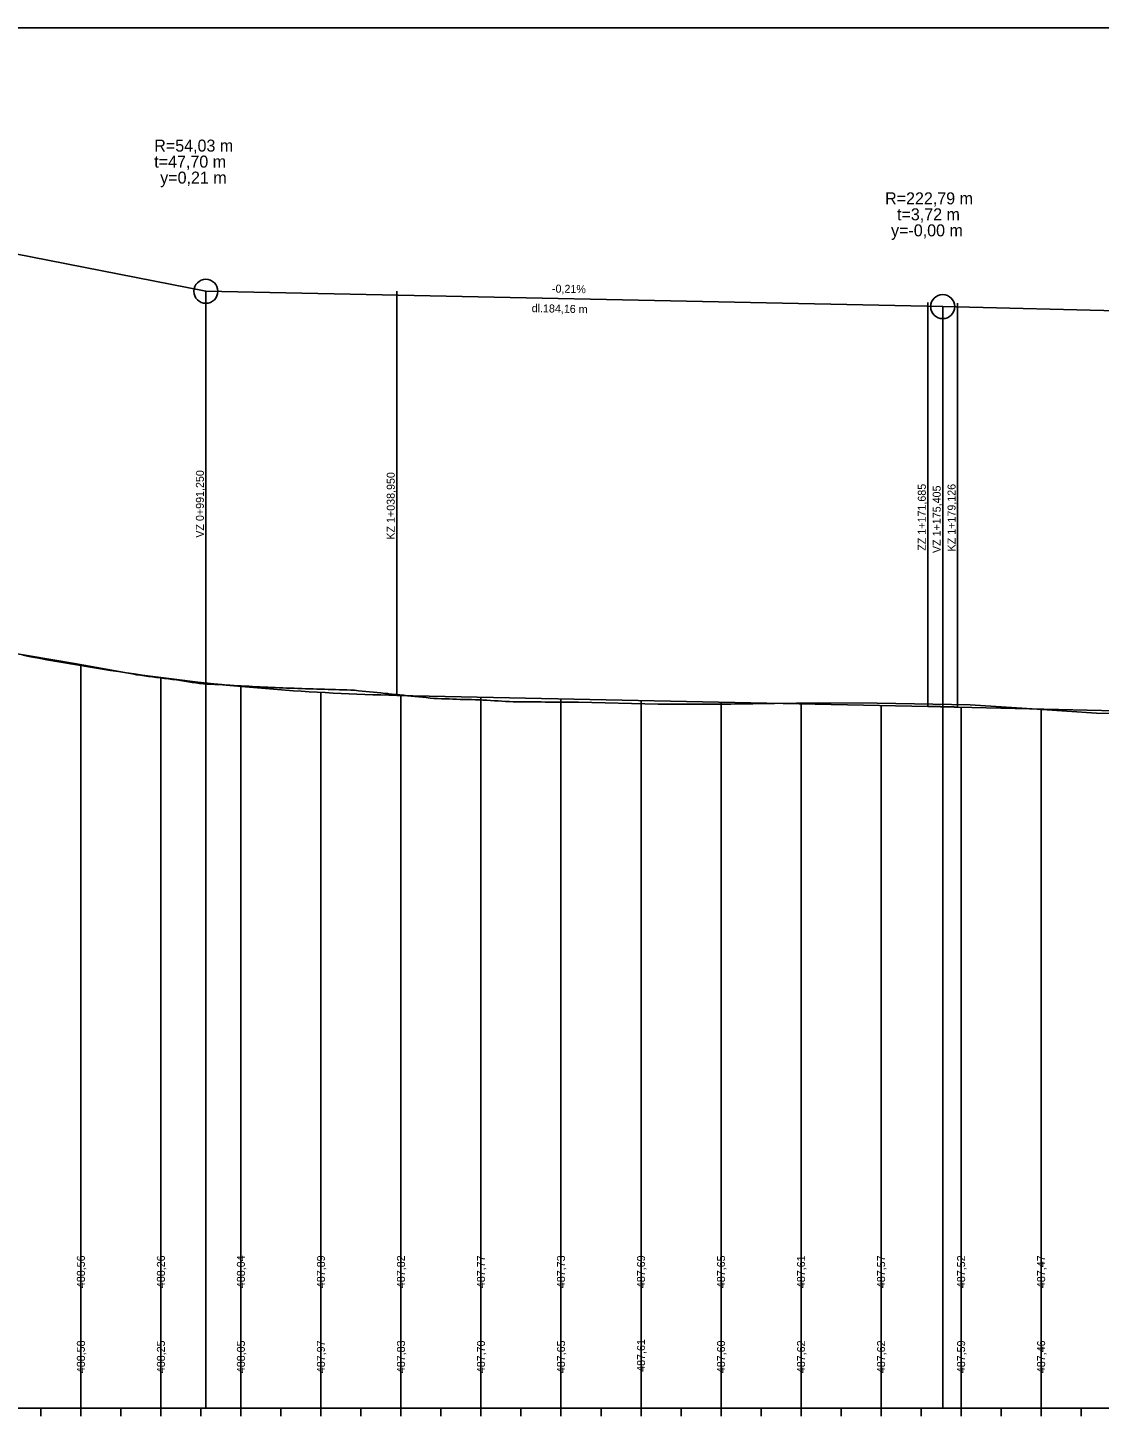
# Model space of a CAD drawing. Extents: x -632716 to -629545, y -1094726 to -1088285.
# Drawn here: x -631536.7 to -631269, y -1091019.4 to -1090670.2 of the extents above; entities that cross this region are included whole.
import ezdxf

# ---------------------------------------------------------------- set-up
doc = ezdxf.new("R2010")
doc.units = 0
for name, color, linetype in [('20', 7, 'Continuous'), ('Default', 7, 'Continuous'), ('formát', 7, 'Continuous'), ('NIVELETA_VYSKY', 7, 'Continuous'), ('REZ_TENKA', 7, 'Continuous'), ('REZ_TLUSTA', 7, 'Continuous'), ('SKLONY_NIVELETA', 7, 'Continuous'), ('SKLONY_POPIS', 7, 'Continuous'), ('TECNY_NIVELETA', 7, 'Continuous'), ('TEREN_VYSKY', 7, 'Continuous'), ('VOZOVKA', 7, 'Continuous')]:
    doc.layers.add(name, color=color, linetype=linetype)

msp = doc.modelspace()

# ---------------------------------------------------------------- linework, layer by layer
at = {"layer": '20'}
for points in [[(-631523.46, -1090829.61), (-631523.46, -1090965.2), (-631523.46, -1091015.2), (-631523.46, -1090955.2)], [(-631503.46, -1090832.58), (-631503.46, -1090965.2), (-631503.46, -1091015.2), (-631503.46, -1090955.2)], [(-631483.46, -1090834.8), (-631483.46, -1090965.2), (-631483.46, -1091015.2), (-631483.46, -1090955.2)], [(-631463.46, -1090836.29), (-631463.46, -1090965.2), (-631463.46, -1091015.2), (-631463.46, -1090955.2)], [(-631443.46, -1090837.04), (-631443.46, -1090965.2), (-631443.46, -1091015.2), (-631443.46, -1090955.2)], [(-631423.46, -1090837.46), (-631423.46, -1090965.2), (-631423.46, -1091015.2), (-631423.46, -1090955.2)], [(-631403.46, -1090837.88), (-631403.46, -1090965.2), (-631403.46, -1091015.2), (-631403.46, -1090955.2)], [(-631383.46, -1090838.29), (-631383.46, -1090965.2), (-631383.46, -1091015.2), (-631383.46, -1090955.2)], [(-631363.46, -1090838.71), (-631363.46, -1090965.2), (-631363.46, -1091015.2), (-631363.46, -1090955.2)], [(-631343.46, -1090839.13), (-631343.46, -1090965.2), (-631343.46, -1091015.2), (-631343.46, -1090955.2)], [(-631323.46, -1090839.54), (-631323.46, -1090965.2), (-631323.46, -1091015.2), (-631323.46, -1090955.2)], [(-631303.46, -1090839.98), (-631303.46, -1090965.2), (-631303.46, -1091015.2), (-631303.46, -1090955.2)], [(-631283.46, -1090840.46), (-631283.46, -1090965.2), (-631283.46, -1091015.2), (-631283.46, -1090955.2)]]:
    msp.add_lwpolyline(points, dxfattribs=at)
at = {"layer": 'Default'}
for p, q in [((-631444.51, -1090837.02), (-631311.78, -1090839.79)), ((-631444.51, -1090837.02), (-631311.78, -1090839.79)), ((-631304.34, -1090839.95), (-631176.44, -1090843.05)), ((-631304.34, -1090839.95), (-631176.44, -1090843.05))]:
    msp.add_line(p, q, dxfattribs=at)
for points in [[(-631537.93, -1090827), (-631535.94, -1090827.38), (-631533.95, -1090827.75), (-631531.96, -1090828.12), (-631529.98, -1090828.48), (-631527.99, -1090828.83), (-631526, -1090829.18), (-631524.01, -1090829.51), (-631522.03, -1090829.84), (-631520.04, -1090830.17), (-631518.05, -1090830.48), (-631516.06, -1090830.79), (-631514.08, -1090831.09), (-631512.09, -1090831.39), (-631510.1, -1090831.67), (-631508.11, -1090831.95), (-631506.13, -1090832.22), (-631504.14, -1090832.49), (-631502.15, -1090832.74), (-631500.16, -1090832.99), (-631498.18, -1090833.24), (-631496.19, -1090833.47), (-631494.2, -1090833.7), (-631490.23, -1090834.13), (-631488.24, -1090834.34), (-631486.25, -1090834.54), (-631484.26, -1090834.73), (-631482.28, -1090834.91), (-631480.29, -1090835.09), (-631478.3, -1090835.26), (-631476.31, -1090835.42), (-631474.33, -1090835.58), (-631472.34, -1090835.72), (-631470.35, -1090835.86), (-631468.36, -1090836), (-631466.38, -1090836.12), (-631464.39, -1090836.24), (-631462.4, -1090836.35), (-631460.41, -1090836.45), (-631458.43, -1090836.55), (-631456.44, -1090836.64), (-631454.45, -1090836.72), (-631452.46, -1090836.8), (-631450.48, -1090836.86), (-631448.49, -1090836.92), (-631446.5, -1090836.97), (-631444.51, -1090837.02)], [(-631537.93, -1090827), (-631535.94, -1090827.38), (-631533.95, -1090827.75), (-631531.96, -1090828.12), (-631529.98, -1090828.48), (-631527.99, -1090828.83), (-631526, -1090829.18), (-631524.01, -1090829.51), (-631522.03, -1090829.84), (-631520.04, -1090830.17), (-631518.05, -1090830.48), (-631516.06, -1090830.79), (-631514.08, -1090831.09), (-631512.09, -1090831.39), (-631510.1, -1090831.67), (-631508.11, -1090831.95), (-631506.13, -1090832.22), (-631504.14, -1090832.49), (-631502.15, -1090832.74), (-631500.16, -1090832.99), (-631498.18, -1090833.24), (-631496.19, -1090833.47), (-631494.2, -1090833.7), (-631490.23, -1090834.13), (-631488.24, -1090834.34), (-631486.25, -1090834.54), (-631484.26, -1090834.73), (-631482.28, -1090834.91), (-631480.29, -1090835.09), (-631478.3, -1090835.26), (-631476.31, -1090835.42), (-631474.33, -1090835.58), (-631472.34, -1090835.72), (-631470.35, -1090835.86), (-631468.36, -1090836), (-631466.38, -1090836.12), (-631464.39, -1090836.24), (-631462.4, -1090836.35), (-631460.41, -1090836.45), (-631458.43, -1090836.55), (-631456.44, -1090836.64), (-631454.45, -1090836.72), (-631452.46, -1090836.8), (-631450.48, -1090836.86), (-631448.49, -1090836.92), (-631446.5, -1090836.97), (-631444.51, -1090837.02)], [(-631311.78, -1090839.79), (-631311.62, -1090839.79), (-631311.47, -1090839.79), (-631311.31, -1090839.8), (-631311.16, -1090839.8), (-631311, -1090839.8), (-631310.85, -1090839.81), (-631310.69, -1090839.81), (-631310.54, -1090839.81), (-631310.38, -1090839.82), (-631310.23, -1090839.82), (-631310.07, -1090839.82), (-631309.92, -1090839.83), (-631309.76, -1090839.83), (-631309.61, -1090839.83), (-631309.45, -1090839.84), (-631309.3, -1090839.84), (-631309.14, -1090839.84), (-631308.99, -1090839.85), (-631308.83, -1090839.85), (-631308.68, -1090839.85), (-631308.52, -1090839.86), (-631308.37, -1090839.86), (-631308.21, -1090839.86), (-631307.9, -1090839.87), (-631307.75, -1090839.87), (-631307.59, -1090839.88), (-631307.44, -1090839.88), (-631307.28, -1090839.88), (-631307.13, -1090839.89), (-631306.97, -1090839.89), (-631306.82, -1090839.9), (-631306.66, -1090839.9), (-631306.51, -1090839.9), (-631306.35, -1090839.91), (-631306.2, -1090839.91), (-631306.04, -1090839.91), (-631305.89, -1090839.92), (-631305.73, -1090839.92), (-631305.58, -1090839.92), (-631305.42, -1090839.93), (-631305.27, -1090839.93), (-631305.11, -1090839.94), (-631304.96, -1090839.94), (-631304.8, -1090839.94), (-631304.65, -1090839.95), (-631304.49, -1090839.95), (-631304.34, -1090839.95)], [(-631311.78, -1090839.79), (-631311.62, -1090839.79), (-631311.47, -1090839.79), (-631311.31, -1090839.8), (-631311.16, -1090839.8), (-631311, -1090839.8), (-631310.85, -1090839.81), (-631310.69, -1090839.81), (-631310.54, -1090839.81), (-631310.38, -1090839.82), (-631310.23, -1090839.82), (-631310.07, -1090839.82), (-631309.92, -1090839.83), (-631309.76, -1090839.83), (-631309.61, -1090839.83), (-631309.45, -1090839.84), (-631309.3, -1090839.84), (-631309.14, -1090839.84), (-631308.99, -1090839.85), (-631308.83, -1090839.85), (-631308.68, -1090839.85), (-631308.52, -1090839.86), (-631308.37, -1090839.86), (-631308.21, -1090839.86), (-631307.9, -1090839.87), (-631307.75, -1090839.87), (-631307.59, -1090839.88), (-631307.44, -1090839.88), (-631307.28, -1090839.88), (-631307.13, -1090839.89), (-631306.97, -1090839.89), (-631306.82, -1090839.9), (-631306.66, -1090839.9), (-631306.51, -1090839.9), (-631306.35, -1090839.91), (-631306.2, -1090839.91), (-631306.04, -1090839.91), (-631305.89, -1090839.92), (-631305.73, -1090839.92), (-631305.58, -1090839.92), (-631305.42, -1090839.93), (-631305.27, -1090839.93), (-631305.11, -1090839.94), (-631304.96, -1090839.94), (-631304.8, -1090839.94), (-631304.65, -1090839.95), (-631304.49, -1090839.95), (-631304.34, -1090839.95)]]:
    msp.add_lwpolyline(points, dxfattribs=at)
at = {"layer": 'formát'}
msp.add_lwpolyline([(-632585.29, -1091264.2), (-630730.3, -1091264.2), (-630730.3, -1090670.2), (-632585.29, -1090670.2)], close=True, dxfattribs=at)
at = {"layer": 'REZ_TENKA'}
for p, q in [((-631533.46, -1091017.2), (-631533.46, -1091015.2)), ((-631523.46, -1091017.2), (-631523.46, -1091015.2)), ((-631513.46, -1091017.2), (-631513.46, -1091015.2)), ((-631503.46, -1091017.2), (-631503.46, -1091015.2)), ((-631493.46, -1091017.2), (-631493.46, -1091015.2)), ((-631473.46, -1091017.2), (-631473.46, -1091015.2)), ((-631463.46, -1091017.2), (-631463.46, -1091015.2)), ((-631453.46, -1091017.2), (-631453.46, -1091015.2)), ((-631443.46, -1091017.2), (-631443.46, -1091015.2)), ((-631433.46, -1091017.2), (-631433.46, -1091015.2)), ((-631423.46, -1091017.2), (-631423.46, -1091015.2)), ((-631413.46, -1091017.2), (-631413.46, -1091015.2)), ((-631403.46, -1091017.2), (-631403.46, -1091015.2)), ((-631393.46, -1091017.2), (-631393.46, -1091015.2)), ((-631373.46, -1091017.2), (-631373.46, -1091015.2)), ((-631363.46, -1091017.2), (-631363.46, -1091015.2)), ((-631353.46, -1091017.2), (-631353.46, -1091015.2)), ((-631343.46, -1091017.2), (-631343.46, -1091015.2)), ((-631333.46, -1091017.2), (-631333.46, -1091015.2)), ((-631323.46, -1091017.2), (-631323.46, -1091015.2)), ((-631313.46, -1091017.2), (-631313.46, -1091015.2)), ((-631303.46, -1091017.2), (-631303.46, -1091015.2)), ((-631293.46, -1091017.2), (-631293.46, -1091015.2)), ((-631273.46, -1091017.2), (-631273.46, -1091015.2))]:
    msp.add_line(p, q, dxfattribs=at)
at = {"layer": 'REZ_TLUSTA'}
for p, q in [((-631483.46, -1091017.2), (-631483.46, -1091013.2)), ((-631383.46, -1091017.2), (-631383.46, -1091013.2)), ((-631283.46, -1091017.2), (-631283.46, -1091013.2)), ((-632483.46, -1091015.2), (-630763.46, -1091015.2))]:
    msp.add_line(p, q, dxfattribs=at)
at = {"layer": 'SKLONY_NIVELETA'}
for p, q in [((-631618.66, -1090711.06), (-631492.21, -1090736.03)), ((-631492.21, -1090736.03), (-631492.21, -1091015.2)), ((-631492.21, -1090736.03), (-631308.06, -1090739.86)), ((-631308.06, -1090739.86), (-631308.06, -1091015.2)), ((-631308.06, -1090739.86), (-631139.63, -1090743.94)), ((-631444.51, -1090837.02), (-631311.78, -1090839.79)), ((-631304.34, -1090839.95), (-631176.44, -1090843.05))]:
    msp.add_line(p, q, dxfattribs=at)
for points in [[(-631537.93, -1090827), (-631535.94, -1090827.38), (-631533.95, -1090827.75), (-631531.96, -1090828.12), (-631529.98, -1090828.48), (-631527.99, -1090828.83), (-631526, -1090829.18), (-631524.01, -1090829.51), (-631522.03, -1090829.84), (-631520.04, -1090830.17), (-631518.05, -1090830.48), (-631516.06, -1090830.79), (-631514.08, -1090831.09), (-631512.09, -1090831.39), (-631510.1, -1090831.67), (-631508.11, -1090831.95), (-631506.13, -1090832.22), (-631504.14, -1090832.49), (-631502.15, -1090832.74), (-631500.16, -1090832.99), (-631498.18, -1090833.24), (-631496.19, -1090833.47), (-631494.2, -1090833.7), (-631490.23, -1090834.13), (-631488.24, -1090834.34), (-631486.25, -1090834.54), (-631484.26, -1090834.73), (-631482.28, -1090834.91), (-631480.29, -1090835.09), (-631478.3, -1090835.26), (-631476.31, -1090835.42), (-631474.33, -1090835.58), (-631472.34, -1090835.72), (-631470.35, -1090835.86), (-631468.36, -1090836), (-631466.38, -1090836.12), (-631464.39, -1090836.24), (-631462.4, -1090836.35), (-631460.41, -1090836.45), (-631458.43, -1090836.55), (-631456.44, -1090836.64), (-631454.45, -1090836.72), (-631452.46, -1090836.8), (-631450.48, -1090836.86), (-631448.49, -1090836.92), (-631446.5, -1090836.97), (-631444.51, -1090837.02)], [(-631311.78, -1090839.79), (-631311.62, -1090839.79), (-631311.47, -1090839.79), (-631311.31, -1090839.8), (-631311.16, -1090839.8), (-631311, -1090839.8), (-631310.85, -1090839.81), (-631310.69, -1090839.81), (-631310.54, -1090839.81), (-631310.38, -1090839.82), (-631310.23, -1090839.82), (-631310.07, -1090839.82), (-631309.92, -1090839.83), (-631309.76, -1090839.83), (-631309.61, -1090839.83), (-631309.45, -1090839.84), (-631309.3, -1090839.84), (-631309.14, -1090839.84), (-631308.99, -1090839.85), (-631308.83, -1090839.85), (-631308.68, -1090839.85), (-631308.52, -1090839.86), (-631308.37, -1090839.86), (-631308.21, -1090839.86), (-631307.9, -1090839.87), (-631307.75, -1090839.87), (-631307.59, -1090839.88), (-631307.44, -1090839.88), (-631307.28, -1090839.88), (-631307.13, -1090839.89), (-631306.97, -1090839.89), (-631306.82, -1090839.9), (-631306.66, -1090839.9), (-631306.51, -1090839.9), (-631306.35, -1090839.91), (-631306.2, -1090839.91), (-631306.04, -1090839.91), (-631305.89, -1090839.92), (-631305.73, -1090839.92), (-631305.58, -1090839.92), (-631305.42, -1090839.93), (-631305.27, -1090839.93), (-631305.11, -1090839.94), (-631304.96, -1090839.94), (-631304.8, -1090839.94), (-631304.65, -1090839.95), (-631304.49, -1090839.95), (-631304.34, -1090839.95)]]:
    msp.add_lwpolyline(points, dxfattribs=at)
for centre in [(-631492.21, -1090736.03), (-631308.06, -1090739.86)]:
    msp.add_circle(centre, 3, dxfattribs=at)
at = {"layer": 'TECNY_NIVELETA'}
for p, q in [((-631492.21, -1090736.03), (-631492.21, -1090736.03)), ((-631444.51, -1090837.02), (-631444.51, -1090736.02)), ((-631311.78, -1090839.79), (-631311.78, -1090738.79)), ((-631308.06, -1090739.86), (-631308.06, -1090739.86)), ((-631304.34, -1090839.95), (-631304.34, -1090738.95))]:
    msp.add_line(p, q, dxfattribs=at)
at = {"layer": 'VOZOVKA'}
msp.add_lwpolyline([(-631548.29, -1090825.16), (-631525.08, -1090829.09), (-631514.81, -1090830.93), (-631512.54, -1090831.33), (-631511.54, -1090831.51), (-631510.54, -1090831.68), (-631509.54, -1090831.86), (-631509.26, -1090831.91), (-631508.54, -1090832.01), (-631507.54, -1090832.14), (-631506.54, -1090832.28), (-631505.54, -1090832.41), (-631504.54, -1090832.54), (-631503.54, -1090832.67), (-631502.54, -1090832.8), (-631501.54, -1090832.92), (-631500.54, -1090833.05), (-631499.54, -1090833.16), (-631498.99, -1090833.23), (-631498.54, -1090833.3), (-631497.54, -1090833.47), (-631496.6, -1090833.63), (-631495.65, -1090833.78), (-631494.71, -1090833.93), (-631493.77, -1090834.07), (-631493.57, -1090834.1), (-631492.82, -1090834.14), (-631491.88, -1090834.2), (-631490.93, -1090834.25), (-631489.99, -1090834.3), (-631489.05, -1090834.35), (-631488.1, -1090834.41), (-631487.16, -1090834.46), (-631486.21, -1090834.51), (-631485.27, -1090834.56), (-631484.32, -1090834.61), (-631483.38, -1090834.66), (-631482.44, -1090834.71), (-631481.49, -1090834.76), (-631480.55, -1090834.81), (-631479.6, -1090834.86), (-631478.66, -1090834.91), (-631477.72, -1090834.96), (-631476.77, -1090835.01), (-631476.13, -1090835.04), (-631475.83, -1090835.06), (-631474.88, -1090835.09), (-631473.94, -1090835.13), (-631473, -1090835.16), (-631472.05, -1090835.19), (-631471.11, -1090835.23), (-631470.74, -1090835.24), (-631470.16, -1090835.26), (-631469.22, -1090835.29), (-631468.27, -1090835.33), (-631467.33, -1090835.36), (-631466.39, -1090835.39), (-631465.44, -1090835.42), (-631464.5, -1090835.45), (-631463.55, -1090835.48), (-631462.61, -1090835.51), (-631461.67, -1090835.54), (-631460.72, -1090835.57), (-631459.78, -1090835.6), (-631458.83, -1090835.63), (-631457.89, -1090835.66), (-631456.95, -1090835.68), (-631456, -1090835.71), (-631455.4, -1090835.73), (-631455.06, -1090835.76), (-631454.11, -1090835.86), (-631453.17, -1090835.96), (-631452.22, -1090836.05), (-631451.28, -1090836.15), (-631450.34, -1090836.24), (-631449.39, -1090836.34), (-631448.45, -1090836.43), (-631447.5, -1090836.52), (-631446.79, -1090836.59), (-631446.56, -1090836.61), (-631445.62, -1090836.71), (-631444.67, -1090836.81), (-631443.73, -1090836.91), (-631442.78, -1090837.01), (-631441.84, -1090837.11), (-631440.9, -1090837.21), (-631439.95, -1090837.3), (-631439.01, -1090837.4), (-631438.06, -1090837.5), (-631437.12, -1090837.59), (-631436.17, -1090837.69), (-631435.23, -1090837.78), (-631434.82, -1090837.82), (-631434.29, -1090837.84), (-631433.34, -1090837.87), (-631432.4, -1090837.9), (-631431.45, -1090837.93), (-631430.51, -1090837.96), (-631429.57, -1090837.99), (-631428.62, -1090838.02), (-631427.68, -1090838.04), (-631426.73, -1090838.07), (-631425.79, -1090838.1), (-631424.85, -1090838.12), (-631423.9, -1090838.15), (-631423.59, -1090838.15), (-631422.96, -1090838.19), (-631422.01, -1090838.25), (-631421.07, -1090838.31), (-631420.12, -1090838.36), (-631419.18, -1090838.42), (-631418.24, -1090838.47), (-631417.29, -1090838.52), (-631416.35, -1090838.56), (-631415.42, -1090838.61), (-631415.4, -1090838.61), (-631414.4, -1090838.62), (-631413.4, -1090838.64), (-631412.4, -1090838.65), (-631411.4, -1090838.66), (-631410.4, -1090838.67), (-631409.4, -1090838.68), (-631408.4, -1090838.68), (-631407.4, -1090838.69), (-631406.4, -1090838.69), (-631405.4, -1090838.69), (-631404.4, -1090838.69), (-631403.4, -1090838.69), (-631402.4, -1090838.69), (-631401.4, -1090838.69), (-631400.4, -1090838.69), (-631399.12, -1090838.69), (-631379.2, -1090839.24), (-631361.01, -1090839.24), (-631339.11, -1090838.88), (-631324.47, -1090838.99), (-631301.17, -1090839.37), (-631284.45, -1090840.48), (-631269.63, -1090841.48), (-631250.49, -1090841.96)], dxfattribs=at)

# ---------------------------------------------------------------- texts
at = {"layer": 'NIVELETA_VYSKY'}
for s, p in [('488,56', (-631522.46, -1090985.2)), ('488,26', (-631502.46, -1090985.2)), ('488,04', (-631482.46, -1090985.2)), ('487,89', (-631462.46, -1090985.2)), ('487,82', (-631442.46, -1090985.2)), ('487,77', (-631422.46, -1090985.2)), ('487,73', (-631402.46, -1090985.2)), ('487,69', (-631382.46, -1090985.2)), ('487,65', (-631362.46, -1090985.2)), ('487,61', (-631342.46, -1090985.2)), ('487,57', (-631322.46, -1090985.2)), ('487,52', (-631302.46, -1090985.2)), ('487,47', (-631282.46, -1090985.2))]:
    msp.add_text(s, height=2, rotation=90, dxfattribs=at).set_placement(p)
at = {"layer": 'SKLONY_POPIS'}
for s, p in [('R=54,03 m', (-631505.12, -1090701.11)), ('t=47,70 m', (-631505.12, -1090705.11)), ('y=0,21 m', (-631503.63, -1090709.11)), ('R=222,79 m', (-631322.46, -1090714.29)), ('t=3,72 m', (-631319.48, -1090718.29)), ('y=-0,00 m', (-631320.97, -1090722.29))]:
    msp.add_text(s, height=3, dxfattribs=at).set_placement(p)
for s, rotation, p in [('-0,21%', 358.8058, (-631405.73, -1090736.33)), ('dl.184,16 m', 358.8058, (-631410.8, -1090741.22)), ('VZ 0+991,250', 90, (-631492.71, -1090797.61)), ('KZ 1+038,950', 90, (-631445.01, -1090798.1)), ('ZZ 1+171,685', 90, (-631312.28, -1090800.87)), ('VZ 1+175,405', 90, (-631308.56, -1090801.45)), ('KZ 1+179,126', 90, (-631304.84, -1090801.04))]:
    msp.add_text(s, height=2, rotation=rotation, dxfattribs=at).set_placement(p)
at = {"layer": 'TEREN_VYSKY'}
for s, p in [('488,58', (-631522.46, -1091006.46)), ('488,25', (-631502.46, -1091006.46)), ('488,05', (-631482.46, -1091006.46)), ('487,97', (-631462.46, -1091006.46)), ('487,83', (-631442.46, -1091006.46)), ('487,70', (-631422.46, -1091006.46)), ('487,65', (-631402.46, -1091006.46)), ('487,61', (-631382.46, -1091006.12)), ('487,60', (-631362.46, -1091006.46)), ('487,62', (-631342.46, -1091006.46)), ('487,62', (-631322.46, -1091006.46)), ('487,59', (-631302.46, -1091006.46)), ('487,46', (-631282.46, -1091006.46))]:
    msp.add_text(s, height=2, rotation=90, dxfattribs=at).set_placement(p)

doc.saveas('drawing.dxf')
